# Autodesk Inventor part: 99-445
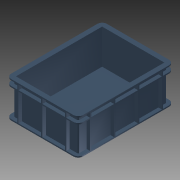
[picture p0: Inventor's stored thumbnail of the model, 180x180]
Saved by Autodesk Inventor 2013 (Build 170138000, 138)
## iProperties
Created: 2004-11
Part Number: 99-445
Document SubType Name: Modeling
Designer: Autodesk, Inc.
Manufacturer: Standard
Standards Organization: Custom
Description: TOTE, EXPANDABLE
Mass: 1848.2 g
Surface Area: 7428.52 cm^2
Volume: 1848.2 cm^3
Density: 1 g/cm^3
Material: Allgemein
CAGE: 1LJX3
Dept. ID: Product Design
Description #2: ---
Finish #1: ---
Finish #2: ---
Material ID: ---
Project Number: ---
Author: Autodesk, Inc.
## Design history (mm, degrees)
sketch "Sketch1"
  geometry: L1 (-150, 200)-(150, 200); L2 (150, 200)-(150, -200); L3 (150, -200)-(-150, -200); L4 (-150, -200)-(-150, 200); 3 further points
  constraints: 8 end point, 2 midpoint, 2 parallel, 1 horizontal, 1 horizontal alignment, 1 perpendicular, 1 vertical alignment
  dimensions: "d0" = 300 distance of L1.start L1.end; "d1" = 400 distance of L3.end L1.start
extrude "Extrusion1" new body sketch "Sketch1" distance "d2" = 150; taper "d3" = 0 deg
workplane "Work Plane1"
workplane "Work Plane2"
fillet "Fillet1" dims "d6" = 20
sketch "Sketch2"
  geometry: L1 (150, -180)-(150, 180) reference; L2 (130, 200)-(-130, 200) reference; L3 (-150, 180)-(-150, -180) reference; L4 (-130, -200)-(130, -200) reference; L5 (-130, 185)-(130, 185); L6 (135, 180)-(135, -180); L7 (130, -185)-(-130, -185); L8 (-135, -180)-(-135, 180); A1 r 20 centre (130, -180) between (130, -200) and (150, -180) reference; A2 r 20 centre (130, 180) between (150, 180) and (130, 200) reference; A3 r 20 centre (-130, 180) between (-130, 200) and (-150, 180) reference; A4 r 20 centre (-130, -180) between (-150, -180) and (-130, -200) reference; A5 r 5 centre (-130, 180) between (-130, 185) and (-135, 180); A6 r 5 centre (130, 180) between (135, 180) and (130, 185); A7 r 5 centre (130, -180) between (130, -185) and (135, -180); A8 r 5 centre (-130, -180) between (-135, -180) and (-130, -185)
  constraints: 8 end point, 8 point on circle, 4 centre point, 7 other
  dimensions: "d7" = 15 distance between parallel lines of L3 L8
extrude "Extrusion2" cut sketch "Sketch2" stored distance "d8" = 212; taper "d9" = 0 deg
workplane "Work Plane3"
workplane "Work Plane4"
extrude "Extrusion3" cut sketch "Sketch2" stored distance "d12" = 212; taper "d13" = 0 deg
shell "Shell1" dims "d14" = 5
fillet "Fillet2" dims "d15" = 5
sketch "Sketch3"
  geometry: L1 (-25, 0)-(-25, 360) reference; L2 (115, 360)-(115, 0) reference; L3 (-25, 35)-(115, 35); L4 (115, 35)-(115, 30); L5 (115, 30)-(-25, 30); L6 (-25, 30)-(-25, 35); L7 (115, 0)-(0, 0) reference
  constraints: 8 end point, 2 parallel, 2 point on line, 1 horizontal, 1 perpendicular
  dimensions: "d16" = 5 distance between parallel lines of L5 L3; "d17" = 30 distance between parallel lines of L7 L5
extrude "Extrusion4" join sketch "Sketch3" stored distance "d18" = 10; taper "d19" = 0 deg
pattern_linear "Rectangular Pattern1" dims "d22" = 300 (= -2 x d6 + d1 - 2 x d17)
mirror "Mirror1"
sketch "Sketch4"
  geometry: L1 (0, 140)-(260, 140) reference; L2 (260, 0)-(0, 0) reference; L3 (25, 0)-(30, 0); L4 (30, 0)-(30, 140); L5 (30, 140)-(25, 140); L6 (25, 140)-(25, 0); L7 (-5, 0)-(-5, 115) reference
  constraints: 8 end point, 2 parallel, 2 point on line, 1 horizontal, 1 perpendicular
  dimensions: "d23" = 5 distance between parallel lines of L4 L6; "d24" = 30 distance between parallel lines of L7 L6
extrude "Extrusion5" join sketch "Sketch4" stored distance "d25" = 10; taper "d26" = 0 deg
pattern_linear "Rectangular Pattern2" dims "d29" = 200 (= -2 x d6 + d0 - 2 x d24)
mirror "Mirror2"
body "Solid1"
node "Projected Loop1"
other parameters: "d4" = -5, "d10" = -5, "d11" = -5
